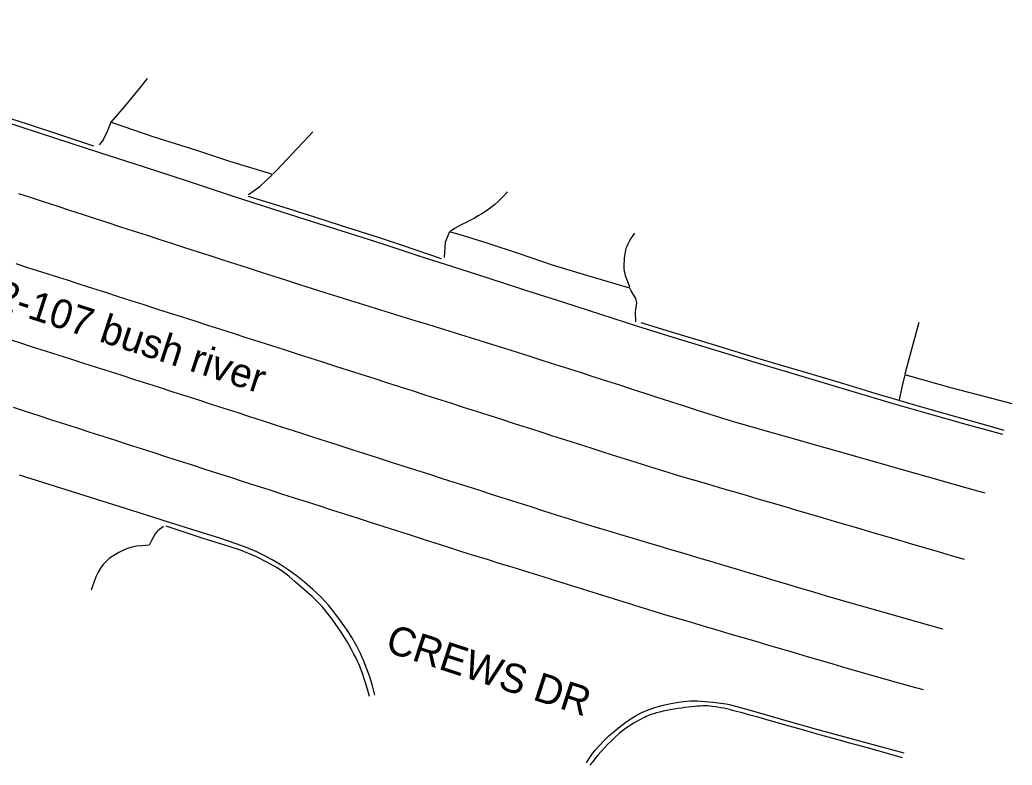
# Model space of a CAD drawing. Extents: x 1961683 to 1977751, y 798292 to 805767.
# Drawn here: x 1964364.3 to 1964549, y 799252.4 to 799391.1 of the extents above; entities that cross this region are included whole.
import ezdxf

# ---------------------------------------------------------------- set-up
doc = ezdxf.new("R2010")
doc.units = 0
for name, color, linetype in [('RD_EX_Road', 7, 'Continuous'), ('RD_EX_Road_Paint', 7, 'Continuous'), ('RD_TX_RoadID', 7, 'Continuous')]:
    doc.layers.add(name, color=color, linetype=linetype)

msp = doc.modelspace()

# ---------------------------------------------------------------- linework, layer by layer
at = {"layer": 'RD_EX_Road'}
for points in [[(1964378.07, 799367.65), (1964371.69, 799369.74), (1964365.89, 799371.63), (1964360.68, 799373.34), (1964356.05, 799374.84), (1964351.78, 799376.24), (1964347.63, 799377.59), (1964343.6, 799378.91), (1964339.69, 799380.19), (1964335.8, 799381.46), (1964331.84, 799382.75), (1964327.8, 799384.05), (1964323.69, 799385.36), (1964319.44, 799386.72), (1964315, 799388.13), (1964310.37, 799389.61), (1964305.55, 799391.14)], [(1964387.99, 799380.23), (1964386.53, 799378.41), (1964383.68, 799374.93), (1964381.28, 799372.12)], [(1964547.27, 799313.92), (1964540.49, 799315.8), (1964533.43, 799317.79), (1964526.51, 799319.79), (1964519.86, 799321.75), (1964513.63, 799323.6), (1964507.45, 799325.45), (1964500.96, 799327.41), (1964494.08, 799329.5), (1964486.71, 799331.75), (1964479.33, 799334.05), (1964472.41, 799336.28), (1964465.54, 799338.51), (1964458.32, 799340.83), (1964451.26, 799343.09), (1964444.86, 799345.14), (1964438.64, 799347.15), (1964432.12, 799349.29), (1964425.44, 799351.45), (1964418.77, 799353.55), (1964411.72, 799355.78), (1964403.89, 799358.32), (1964395.67, 799361.01), (1964387.46, 799363.68), (1964379.19, 799366.36), (1964370.81, 799369.09), (1964361.68, 799372.08)], [(1964406.83, 799358.61), (1964408.95, 799360.13), (1964411.31, 799362.32), (1964410.54, 799362.58), (1964403.37, 799364.78), (1964397.22, 799366.8), (1964389.25, 799369.31), (1964381.53, 799371.95), (1964381.23, 799372.06), (1964380.5, 799370.37), (1964379.77, 799368.83), (1964379.04, 799367.85)], [(1964418.8, 799370.3), (1964417.93, 799369.38), (1964412.08, 799363.11), (1964411.46, 799362.47)], [(1964442.77, 799346.66), (1964435.53, 799349.12), (1964431.43, 799350.47), (1964423.98, 799352.86), (1964419.16, 799354.39), (1964413.45, 799356.19), (1964406.84, 799358.27)], [(1964455.03, 799359.09), (1964454.87, 799358.91), (1964454.24, 799358.23), (1964453.77, 799357.74), (1964453.26, 799357.26), (1964452.73, 799356.78), (1964452.17, 799356.32), (1964451.58, 799355.86), (1964450.95, 799355.43), (1964450.3, 799355.01), (1964449.62, 799354.62), (1964448.9, 799354.24), (1964448.15, 799353.84), (1964447.36, 799353.43), (1964446.54, 799353.01), (1964445.78, 799352.62), (1964445.18, 799352.29), (1964444.73, 799352.01), (1964444.43, 799351.8)], [(1964478.95, 799334.94), (1964478.91, 799336.78), (1964479.15, 799338.46), (1964478.93, 799339.28), (1964478.1, 799340.69), (1964477.84, 799341.16), (1964476.37, 799341.6), (1964469.85, 799343.52), (1964463.63, 799345.43), (1964457.27, 799347.6), (1964451.26, 799349.53), (1964446.06, 799351.15), (1964444.29, 799351.66), (1964443.48, 799349.74), (1964443.25, 799346.9)], [(1964478.71, 799351.43), (1964478.39, 799350.97), (1964478.05, 799350.42), (1964477.74, 799349.86), (1964477.47, 799349.35), (1964477.27, 799348.91), (1964477.11, 799348.54), (1964477.01, 799348.24), (1964476.95, 799347.95), (1964476.89, 799347.6), (1964476.84, 799347.2), (1964476.8, 799346.75), (1964476.76, 799346.27), (1964476.74, 799345.8), (1964476.74, 799345.33), (1964476.74, 799344.87), (1964476.81, 799344.32), (1964477, 799343.55), (1964477.32, 799342.58), (1964477.75, 799341.4)], [(1964547.51, 799314.7), (1964543.69, 799315.78), (1964538.78, 799317.17), (1964533.96, 799318.53), (1964530.03, 799319.66), (1964526.94, 799320.56), (1964523.7, 799321.53), (1964521.7, 799322.14), (1964517.71, 799323.36), (1964512.03, 799325.05), (1964506.08, 799326.81), (1964501.04, 799328.3), (1964496.28, 799329.73), (1964491.21, 799331.28), (1964486.19, 799332.82), (1964479.94, 799334.72)], [(1964531.63, 799334.8), (1964529.96, 799328.66), (1964529.05, 799325.18)], [(1964549.02, 799319.62), (1964545.48, 799320.56), (1964537.83, 799322.59), (1964530.17, 799324.71), (1964529.01, 799325.03), (1964528.51, 799322.73), (1964527.98, 799320.39)], [(1964430.38, 799265.42), (1964429.93, 799267.12), (1964429.41, 799268.8), (1964428.83, 799270.44), (1964428.32, 799271.74), (1964428.03, 799272.44), (1964427.69, 799273.16), (1964427.01, 799274.49), (1964426.09, 799276.12), (1964425.06, 799277.7), (1964423.97, 799279.24), (1964422.9, 799280.69), (1964421.72, 799282.14), (1964420.34, 799283.63), (1964418.83, 799285.09), (1964417.27, 799286.45), (1964415.72, 799287.69), (1964414.21, 799288.76), (1964412.73, 799289.72), (1964411.23, 799290.61), (1964409.78, 799291.41), (1964408.4, 799292.09), (1964406.77, 799292.77), (1964404.56, 799293.58), (1964401.49, 799294.6), (1964397.28, 799295.95), (1964392.15, 799297.57), (1964386.3, 799299.42), (1964379.59, 799301.54), (1964371.89, 799303.95), (1964364.23, 799306.37)], [(1964391.03, 799296.83), (1964390.25, 799296.26), (1964389.98, 799296.02), (1964389.79, 799295.82), (1964389.49, 799295.41), (1964389.16, 799294.88), (1964388.79, 799294.19), (1964388.37, 799293.32), (1964386.95, 799293.22), (1964385.96, 799293.11), (1964385.2, 799292.97), (1964384.47, 799292.77), (1964383.67, 799292.46), (1964382.71, 799291.99), (1964381.76, 799291.43), (1964380.96, 799290.88), (1964380.31, 799290.31), (1964379.76, 799289.7), (1964379.28, 799289.03), (1964378.84, 799288.28), (1964378.44, 799287.46), (1964378.08, 799286.53), (1964377.67, 799285.3), (1964377.55, 799284.95)], [(1964429.34, 799265.15), (1964428.97, 799266.53), (1964428.5, 799268.08), (1964427.99, 799269.61), (1964427.5, 799270.89), (1964427.12, 799271.75), (1964426.8, 799272.38), (1964426.48, 799273.02), (1964426.02, 799273.9), (1964425.26, 799275.28), (1964424.1, 799277.15), (1964422.44, 799279.52), (1964420.54, 799281.88), (1964418.67, 799283.77), (1964416.96, 799285.28), (1964415.54, 799286.52), (1964414.36, 799287.53), (1964413.37, 799288.31), (1964412.15, 799289.1), (1964410.27, 799290.13), (1964408.31, 799291.13), (1964406.84, 799291.8), (1964405.32, 799292.38), (1964403.22, 799293.07), (1964400.83, 799293.82), (1964398.43, 799294.58), (1964395.78, 799295.45), (1964391.52, 799296.86)], [(1964469.76, 799252.82), (1964470.26, 799253.58), (1964470.79, 799254.34), (1964471.39, 799255.14), (1964472.13, 799255.99), (1964473, 799256.89), (1964473.95, 799257.81), (1964474.97, 799258.72), (1964476.03, 799259.58), (1964477.1, 799260.37), (1964478.09, 799261.05), (1964479, 799261.62), (1964480.05, 799262.16), (1964481.26, 799262.68), (1964482.52, 799263.11), (1964483.82, 799263.46), (1964485.15, 799263.77), (1964486.51, 799264.05), (1964487.82, 799264.24), (1964489.11, 799264.35), (1964490.43, 799264.35), (1964491.82, 799264.24), (1964493.3, 799264.09), (1964494.8, 799263.9), (1964495.77, 799263.77), (1964496.31, 799263.65), (1964497.5, 799263.35), (1964499.59, 799262.79), (1964502.85, 799261.86), (1964507.3, 799260.57), (1964512.61, 799259.08), (1964518.57, 799257.44), (1964524.27, 799255.89), (1964528.87, 799254.65)], [(1964528.61, 799253.73), (1964527.54, 799254.03), (1964525.54, 799254.59), (1964523.42, 799255.19), (1964521.17, 799255.81), (1964518.8, 799256.47), (1964516.41, 799257.14), (1964514.11, 799257.78), (1964511.91, 799258.4), (1964509.81, 799258.99), (1964507.77, 799259.57), (1964505.77, 799260.13), (1964503.81, 799260.68), (1964501.89, 799261.22), (1964500.16, 799261.7), (1964498.76, 799262.08), (1964497.7, 799262.37), (1964496.97, 799262.57), (1964496.42, 799262.71), (1964495.86, 799262.84), (1964495.31, 799262.95), (1964494.76, 799263.06), (1964494.23, 799263.16), (1964493.72, 799263.24), (1964493.25, 799263.3), (1964492.8, 799263.35), (1964492.36, 799263.38), (1964491.91, 799263.39), (1964491.45, 799263.39), (1964490.97, 799263.37), (1964490.46, 799263.33), (1964489.92, 799263.29), (1964489.34, 799263.23), (1964488.73, 799263.16), (1964488.09, 799263.08), (1964487.43, 799263), (1964486.76, 799262.9), (1964486.07, 799262.8), (1964485.37, 799262.68), (1964484.69, 799262.55), (1964484.03, 799262.4), (1964483.37, 799262.24), (1964482.78, 799262.08), (1964482.29, 799261.95), (1964481.92, 799261.83), (1964481.66, 799261.74), (1964481.44, 799261.65), (1964481.18, 799261.54), (1964480.9, 799261.41), (1964480.58, 799261.26), (1964480.23, 799261.09), (1964479.85, 799260.89), (1964479.44, 799260.67), (1964479.01, 799260.43), (1964478.54, 799260.16), (1964478.06, 799259.86), (1964477.55, 799259.53), (1964477.02, 799259.16), (1964476.46, 799258.73), (1964475.85, 799258.23), (1964475.19, 799257.64), (1964474.48, 799256.98), (1964473.77, 799256.28), (1964473.11, 799255.59), (1964472.48, 799254.9), (1964471.9, 799254.21), (1964471.38, 799253.58), (1964470.97, 799253.07), (1964470.67, 799252.68), (1964470.47, 799252.4), (1964470.44, 799252.36)]]:
    msp.add_lwpolyline(points, dxfattribs=at)
at = {"layer": 'RD_EX_Road_Paint'}
for points in [[(1964364.02, 799358.83), (1964366.39, 799358.05), (1964368.77, 799357.27), (1964371.14, 799356.49), (1964373.51, 799355.71), (1964375.89, 799354.93), (1964378.26, 799354.15), (1964380.64, 799353.38), (1964383.02, 799352.61), (1964385.39, 799351.84), (1964387.77, 799351.08), (1964390.15, 799350.31), (1964392.53, 799349.54), (1964394.9, 799348.77), (1964397.28, 799348.01), (1964399.66, 799347.24), (1964402.04, 799346.47), (1964404.42, 799345.71), (1964406.79, 799344.94), (1964409.17, 799344.17), (1964411.55, 799343.4), (1964413.93, 799342.64), (1964416.31, 799341.87), (1964418.69, 799341.11), (1964421.07, 799340.37), (1964423.46, 799339.63), (1964425.85, 799338.89), (1964428.23, 799338.15), (1964430.62, 799337.41), (1964433.01, 799336.67), (1964435.39, 799335.93), (1964437.78, 799335.19), (1964440.17, 799334.45), (1964442.55, 799333.72), (1964444.94, 799332.98), (1964447.33, 799332.24), (1964449.72, 799331.5), (1964452.1, 799330.76), (1964454.49, 799330.02), (1964456.88, 799329.28), (1964459.25, 799328.51), (1964461.63, 799327.74), (1964464.01, 799326.98), (1964466.39, 799326.21), (1964468.77, 799325.45), (1964471.14, 799324.68), (1964473.52, 799323.91), (1964475.9, 799323.15), (1964478.28, 799322.38), (1964480.66, 799321.61), (1964483.04, 799320.85), (1964485.41, 799320.08), (1964487.79, 799319.31), (1964490.17, 799318.55), (1964492.55, 799317.78), (1964494.93, 799317.02), (1964497.32, 799316.31), (1964499.73, 799315.62), (1964502.13, 799314.94), (1964504.53, 799314.26), (1964506.94, 799313.57), (1964509.34, 799312.89), (1964511.75, 799312.21), (1964514.15, 799311.52), (1964516.55, 799310.84), (1964518.96, 799310.15), (1964521.36, 799309.47), (1964523.76, 799308.79), (1964526.17, 799308.1), (1964528.57, 799307.42), (1964530.97, 799306.74), (1964533.38, 799306.05), (1964535.78, 799305.37), (1964538.18, 799304.69), (1964540.59, 799304), (1964542.99, 799303.32), (1964543.93, 799303.05)], [(1964540.12, 799290.66), (1964537.72, 799291.37), (1964535.32, 799292.07), (1964532.92, 799292.77), (1964530.52, 799293.48), (1964528.13, 799294.18), (1964525.73, 799294.88), (1964523.33, 799295.59), (1964520.93, 799296.29), (1964518.54, 799296.99), (1964516.14, 799297.7), (1964513.74, 799298.4), (1964511.34, 799299.1), (1964508.94, 799299.81), (1964506.55, 799300.51), (1964504.15, 799301.21), (1964501.75, 799301.92), (1964499.35, 799302.62), (1964496.95, 799303.33), (1964494.56, 799304.03), (1964492.16, 799304.73), (1964489.76, 799305.44), (1964487.36, 799306.14), (1964484.97, 799306.84), (1964482.58, 799307.58), (1964480.2, 799308.33), (1964477.81, 799309.08), (1964475.43, 799309.84), (1964473.05, 799310.6), (1964470.67, 799311.37), (1964468.29, 799312.13), (1964465.91, 799312.89), (1964463.53, 799313.65), (1964461.15, 799314.42), (1964458.77, 799315.18), (1964456.39, 799315.94), (1964454.02, 799316.7), (1964451.64, 799317.47), (1964449.26, 799318.23), (1964446.88, 799318.99), (1964444.5, 799319.76), (1964442.12, 799320.52), (1964439.74, 799321.28), (1964437.36, 799322.04), (1964434.98, 799322.81), (1964432.6, 799323.57), (1964430.22, 799324.33), (1964427.84, 799325.09), (1964425.46, 799325.86), (1964423.08, 799326.62), (1964420.7, 799327.38), (1964418.32, 799328.15), (1964415.94, 799328.91), (1964413.56, 799329.67), (1964411.18, 799330.43), (1964408.8, 799331.2), (1964406.42, 799331.96), (1964404.05, 799332.72), (1964401.67, 799333.48), (1964399.29, 799334.25), (1964396.91, 799335.01), (1964394.53, 799335.77), (1964392.15, 799336.54), (1964389.77, 799337.3), (1964387.39, 799338.06), (1964385.01, 799338.82), (1964382.63, 799339.59), (1964380.25, 799340.35), (1964377.87, 799341.11), (1964375.49, 799341.87), (1964373.11, 799342.64), (1964370.73, 799343.4), (1964368.35, 799344.16), (1964365.97, 799344.93), (1964363.59, 799345.69)], [(1964536.1, 799277.7), (1964533.69, 799278.38), (1964531.29, 799279.06), (1964528.88, 799279.73), (1964526.47, 799280.41), (1964524.07, 799281.08), (1964521.66, 799281.76), (1964519.26, 799282.44), (1964516.86, 799283.14), (1964514.46, 799283.85), (1964512.07, 799284.56), (1964509.67, 799285.27), (1964507.28, 799285.98), (1964504.88, 799286.7), (1964502.49, 799287.41), (1964500.09, 799288.13), (1964497.7, 799288.84), (1964495.31, 799289.55), (1964492.91, 799290.27), (1964490.52, 799290.98), (1964488.12, 799291.7), (1964485.73, 799292.41), (1964483.33, 799293.13), (1964480.94, 799293.84), (1964478.54, 799294.55), (1964476.15, 799295.27), (1964473.75, 799295.98), (1964471.36, 799296.7), (1964468.97, 799297.41), (1964466.58, 799298.16), (1964464.2, 799298.92), (1964461.82, 799299.68), (1964459.44, 799300.44), (1964457.06, 799301.2), (1964454.68, 799301.96), (1964452.3, 799302.72), (1964449.92, 799303.48), (1964447.54, 799304.24), (1964445.16, 799305), (1964442.78, 799305.76), (1964440.4, 799306.52), (1964438.02, 799307.28), (1964435.64, 799308.04), (1964433.26, 799308.8), (1964430.88, 799309.57), (1964428.5, 799310.33), (1964426.12, 799311.1), (1964423.74, 799311.87), (1964421.36, 799312.64), (1964418.99, 799313.4), (1964416.61, 799314.17), (1964414.23, 799314.94), (1964411.85, 799315.7), (1964409.47, 799316.47), (1964407.1, 799317.24), (1964404.72, 799318), (1964402.34, 799318.77), (1964399.96, 799319.54), (1964397.58, 799320.31), (1964395.21, 799321.07), (1964392.83, 799321.84), (1964390.45, 799322.6), (1964388.07, 799323.36), (1964385.69, 799324.12), (1964383.31, 799324.89), (1964380.93, 799325.65), (1964378.55, 799326.41), (1964376.17, 799327.17), (1964373.79, 799327.93), (1964371.41, 799328.7), (1964369.03, 799329.46), (1964366.65, 799330.22), (1964364.27, 799330.98), (1964361.89, 799331.75)], [(1964532.54, 799266.38), (1964530.13, 799267.04), (1964527.72, 799267.71), (1964525.31, 799268.37), (1964522.91, 799269.04), (1964520.51, 799269.74), (1964518.11, 799270.45), (1964515.71, 799271.15), (1964513.32, 799271.86), (1964510.92, 799272.56), (1964508.52, 799273.26), (1964506.12, 799273.97), (1964503.72, 799274.67), (1964501.33, 799275.38), (1964498.93, 799276.08), (1964496.53, 799276.78), (1964494.13, 799277.49), (1964491.74, 799278.19), (1964489.34, 799278.9), (1964486.94, 799279.6), (1964484.55, 799280.31), (1964482.16, 799281.05), (1964479.77, 799281.79), (1964477.39, 799282.54), (1964475, 799283.28), (1964472.61, 799284.02), (1964470.23, 799284.76), (1964467.84, 799285.5), (1964465.45, 799286.24), (1964463.07, 799286.98), (1964460.68, 799287.72), (1964458.29, 799288.46), (1964455.91, 799289.2), (1964453.52, 799289.94), (1964451.13, 799290.69), (1964448.75, 799291.43), (1964446.36, 799292.17), (1964443.98, 799292.93), (1964441.6, 799293.69), (1964439.22, 799294.46), (1964436.84, 799295.22), (1964434.46, 799295.98), (1964432.09, 799296.75), (1964429.71, 799297.51), (1964427.33, 799298.27), (1964424.95, 799299.04), (1964422.57, 799299.8), (1964420.19, 799300.56), (1964417.81, 799301.33), (1964415.43, 799302.09), (1964413.05, 799302.85), (1964410.67, 799303.62), (1964408.29, 799304.38), (1964405.91, 799305.14), (1964403.53, 799305.91), (1964401.16, 799306.67), (1964398.78, 799307.44), (1964396.4, 799308.2), (1964394.02, 799308.97), (1964391.64, 799309.73), (1964389.26, 799310.5), (1964386.89, 799311.27), (1964384.51, 799312.03), (1964382.13, 799312.8), (1964379.75, 799313.57), (1964377.37, 799314.33), (1964374.99, 799315.1), (1964372.62, 799315.86), (1964370.24, 799316.63), (1964367.86, 799317.4), (1964365.48, 799318.16), (1964363.1, 799318.93)]]:
    msp.add_lwpolyline(points, dxfattribs=at)

# ---------------------------------------------------------------- texts
at = {"layer": 'RD_TX_RoadID'}
for s, p in [('SOUTH CAROLINA S-32-107 bush river', (1964285.73, 799361.69)), ('CREWS DR', (1964432.09, 799273.58))]:
    msp.add_text(s, height=5.4, rotation=341.9453, dxfattribs=at).set_placement(p)

doc.saveas('drawing.dxf')
